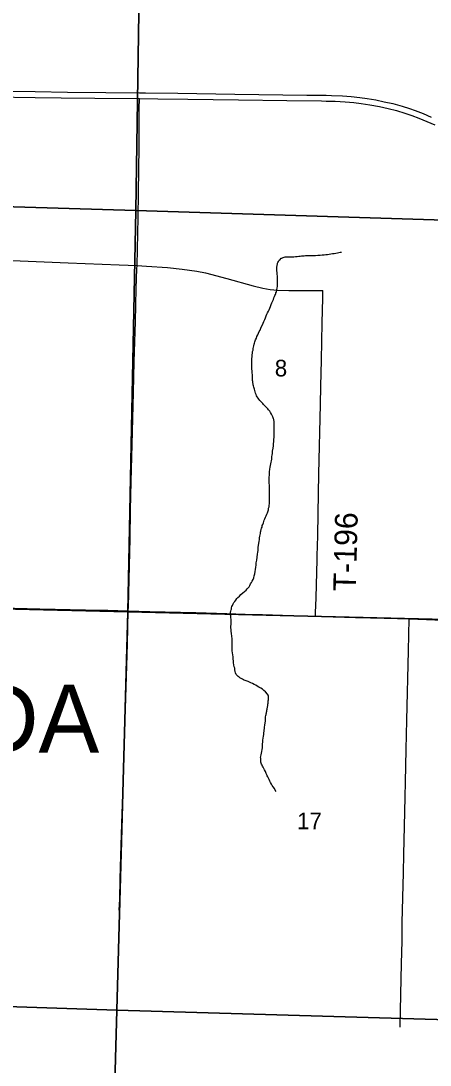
# Model space of a CAD drawing. Extents: x 1587405 to 1714697, y 1028970 to 1155083.
# Drawn here: x 1687215 to 1692632, y 1074942 to 1088767 of the extents above; entities that cross this region are included whole.
import ezdxf

# ---------------------------------------------------------------- set-up
doc = ezdxf.new("R2010")
doc.units = 0
for name, color, linetype in [('GM_X_County_Road', 7, 'Continuous'), ('GM_X_Minor_River', 7, 'Continuous'), ('GM_X_Section', 7, 'Continuous'), ('GM_X_Section_Text', 7, 'Continuous'), ('GM_X_State_Route', 7, 'Continuous'), ('GM_X_Township_Road', 7, 'Continuous'), ('GM_X_Township_Road_Text', 7, 'Continuous'), ('GM_X_Township_Text', 7, 'Continuous')]:
    doc.layers.add(name, color=color, linetype=linetype)

msp = doc.modelspace()

# ---------------------------------------------------------------- linework, layer by layer
at = {"layer": 'GM_X_County_Road'}
for points in [[(1688753, 1085526), (1688767, 1086164), (1688772, 1086492), (1688779, 1087099), (1688782, 1087602), (1688784, 1087737)], [(1682671, 1085938), (1682797, 1085937), (1683536, 1085939), (1683962, 1085937), (1684077, 1085929), (1684289, 1085906), (1684402, 1085886), (1684626, 1085835), (1684770, 1085804), (1685062, 1085754), (1685485, 1085699), (1686089, 1085645), (1686368, 1085629), (1686909, 1085604), (1687204, 1085589), (1687843, 1085564), (1688516, 1085535), (1688753, 1085526)], [(1688636, 1080955), (1688638, 1081011), (1688660, 1081913), (1688668, 1082290), (1688676, 1082668), (1688680, 1082830), (1688688, 1083158), (1688705, 1083847), (1688716, 1084257), (1688731, 1084782), (1688743, 1085225), (1688751, 1085483), (1688753, 1085526)], [(1688753, 1085526), (1688876, 1085521), (1689154, 1085501), (1689350, 1085480), (1689545, 1085452), (1689658, 1085429), (1689943, 1085354), (1690291, 1085258), (1690419, 1085228), (1690516, 1085211), (1690614, 1085202), (1690762, 1085198), (1691212, 1085195)], [(1688518, 1076993), (1688523, 1077140), (1688531, 1077403), (1688540, 1077714), (1688556, 1078272), (1688563, 1078518), (1688590, 1079371), (1688611, 1080092), (1688621, 1080371), (1688625, 1080519), (1688636, 1080955)]]:
    msp.add_lwpolyline(points, dxfattribs=at)
at = {"layer": 'GM_X_Minor_River'}
for points in [[(1690282, 1084388), (1690288, 1084408), (1690292, 1084428), (1690294, 1084448), (1690298, 1084466), (1690302, 1084485), (1690308, 1084501), (1690314, 1084519), (1690320, 1084545), (1690332, 1084565), (1690340, 1084589), (1690350, 1084609), (1690360, 1084631), (1690371, 1084653), (1690381, 1084673), (1690393, 1084697), (1690421, 1084763), (1690431, 1084785), (1690443, 1084815), (1690451, 1084837), (1690461, 1084861), (1690471, 1084883), (1690481, 1084903), (1690492, 1084925), (1690502, 1084943), (1690510, 1084965), (1690520, 1084987), (1690530, 1085012), (1690538, 1085034), (1690548, 1085060), (1690558, 1085078), (1690564, 1085098), (1690572, 1085116), (1690578, 1085130), (1690584, 1085144), (1690588, 1085156), (1690592, 1085168), (1690597, 1085180), (1690601, 1085196), (1690605, 1085212), (1690607, 1085230), (1690611, 1085254), (1690611, 1085274), (1690613, 1085298), (1690613, 1085318), (1690613, 1085340), (1690613, 1085362), (1690611, 1085386), (1690609, 1085413), (1690607, 1085437), (1690605, 1085459), (1690605, 1085477), (1690603, 1085497), (1690603, 1085507), (1690607, 1085527), (1690609, 1085537), (1690611, 1085547), (1690613, 1085557), (1690615, 1085567), (1690624, 1085583), (1690636, 1085597), (1690646, 1085609), (1690660, 1085623), (1690670, 1085627), (1690688, 1085635), (1690700, 1085639), (1690714, 1085641), (1690734, 1085643), (1690754, 1085643), (1690776, 1085643), (1690794, 1085643), (1690810, 1085645), (1690826, 1085645), (1690852, 1085647), (1690871, 1085649), (1690893, 1085650), (1690913, 1085652), (1690931, 1085654), (1690947, 1085656), (1690965, 1085658), (1690983, 1085660), (1691007, 1085660), (1691029, 1085660), (1691051, 1085660), (1691079, 1085660), (1691117, 1085662), (1691145, 1085664), (1691178, 1085666), (1691202, 1085670), (1691228, 1085671), (1691252, 1085673), (1691274, 1085675), (1691296, 1085679), (1691318, 1085681), (1691340, 1085685), (1691360, 1085687), (1691386, 1085693), (1691406, 1085695), (1691425, 1085699), (1691441, 1085703), (1691457, 1085705)], [(1690504, 1082371), (1690506, 1082385), (1690506, 1082401), (1690506, 1082417), (1690508, 1082435), (1690506, 1082453), (1690506, 1082471), (1690506, 1082489), (1690506, 1082509), (1690504, 1082542), (1690504, 1082568), (1690504, 1082592), (1690504, 1082620), (1690502, 1082648), (1690502, 1082678), (1690502, 1082704), (1690505, 1082776), (1690505, 1082798), (1690509, 1082832), (1690515, 1082858), (1690519, 1082881), (1690523, 1082903), (1690529, 1082923), (1690533, 1082943), (1690535, 1082963), (1690537, 1082981), (1690539, 1083001), (1690543, 1083019), (1690545, 1083041), (1690547, 1083069), (1690554, 1083111), (1690558, 1083141), (1690560, 1083169), (1690564, 1083197), (1690564, 1083226), (1690566, 1083256), (1690566, 1083284), (1690566, 1083316), (1690566, 1083342), (1690566, 1083366), (1690566, 1083382), (1690566, 1083400), (1690568, 1083416), (1690568, 1083434), (1690568, 1083452), (1690566, 1083466), (1690564, 1083478), (1690562, 1083488), (1690558, 1083500), (1690554, 1083511), (1690550, 1083525), (1690542, 1083543), (1690532, 1083559), (1690519, 1083583), (1690509, 1083601), (1690495, 1083617), (1690482, 1083631), (1690468, 1083647), (1690454, 1083661), (1690440, 1083675), (1690428, 1083690), (1690416, 1083702), (1690404, 1083714), (1690392, 1083726), (1690380, 1083742), (1690366, 1083758), (1690334, 1083804), (1690328, 1083822), (1690322, 1083840), (1690316, 1083856), (1690310, 1083872), (1690307, 1083889), (1690303, 1083903), (1690297, 1083919), (1690293, 1083935), (1690291, 1083947), (1690289, 1083961), (1690287, 1083971), (1690285, 1083983), (1690285, 1083993), (1690283, 1084005), (1690283, 1084017), (1690283, 1084029), (1690281, 1084043), (1690281, 1084057), (1690279, 1084073), (1690279, 1084085), (1690277, 1084101), (1690275, 1084119), (1690275, 1084135), (1690273, 1084154), (1690271, 1084172), (1690271, 1084192), (1690271, 1084214), (1690271, 1084238), (1690273, 1084264), (1690273, 1084292), (1690275, 1084322), (1690277, 1084344), (1690280, 1084366), (1690282, 1084388)], [(1690057, 1080135), (1690053, 1080153), (1690049, 1080177), (1690045, 1080195), (1690039, 1080217), (1690035, 1080241), (1690031, 1080266), (1690029, 1080292), (1690027, 1080320), (1690023, 1080348), (1690019, 1080374), (1690015, 1080400), (1690013, 1080428), (1690012, 1080472), (1690012, 1080508), (1690010, 1080547), (1690010, 1080585), (1690006, 1080623), (1690002, 1080657), (1689998, 1080687), (1689996, 1080753), (1689998, 1080775), (1689998, 1080795), (1689998, 1080823), (1689998, 1080844), (1689996, 1080862), (1689996, 1080878), (1689994, 1080890), (1689992, 1080902), (1689990, 1080914), (1689991, 1080928), (1689991, 1080942), (1689993, 1080954), (1689999, 1080968), (1690001, 1080980), (1690005, 1080998), (1690009, 1081012), (1690015, 1081028), (1690025, 1081048), (1690035, 1081066), (1690047, 1081082), (1690059, 1081096), (1690075, 1081118), (1690089, 1081132), (1690107, 1081150), (1690128, 1081172), (1690152, 1081194), (1690176, 1081214), (1690196, 1081230), (1690212, 1081248), (1690224, 1081262), (1690236, 1081276), (1690246, 1081292), (1690256, 1081312), (1690268, 1081330), (1690278, 1081350), (1690289, 1081370), (1690297, 1081392), (1690305, 1081418), (1690311, 1081445), (1690317, 1081475), (1690321, 1081505), (1690325, 1081535), (1690329, 1081563), (1690331, 1081591), (1690337, 1081625), (1690348, 1081707), (1690350, 1081733), (1690354, 1081757), (1690356, 1081775), (1690358, 1081798), (1690362, 1081822), (1690364, 1081850), (1690368, 1081874), (1690372, 1081902), (1690374, 1081924), (1690378, 1081946), (1690382, 1081964), (1690386, 1081980), (1690388, 1081996), (1690392, 1082012), (1690396, 1082032), (1690401, 1082050), (1690407, 1082066), (1690411, 1082084), (1690417, 1082100), (1690425, 1082122), (1690431, 1082140), (1690437, 1082156), (1690443, 1082174), (1690453, 1082195), (1690461, 1082215), (1690471, 1082235), (1690479, 1082253), (1690485, 1082267), (1690489, 1082279), (1690491, 1082293), (1690495, 1082315), (1690500, 1082335), (1690502, 1082353), (1690504, 1082371)], [(1690595, 1078564), (1690583, 1078582), (1690571, 1078604), (1690555, 1078626), (1690543, 1078643), (1690533, 1078661), (1690521, 1078683), (1690511, 1078703), (1690501, 1078723), (1690493, 1078743), (1690485, 1078759), (1690477, 1078771), (1690469, 1078787), (1690461, 1078803), (1690451, 1078828), (1690439, 1078850), (1690431, 1078868), (1690421, 1078886), (1690413, 1078900), (1690407, 1078914), (1690401, 1078926), (1690397, 1078938), (1690393, 1078952), (1690391, 1078962), (1690391, 1078974), (1690391, 1078988), (1690391, 1079004), (1690389, 1079016), (1690391, 1079030), (1690395, 1079050), (1690400, 1079072), (1690412, 1079141), (1690414, 1079159), (1690414, 1079173), (1690414, 1079195), (1690416, 1079219), (1690420, 1079243), (1690422, 1079269), (1690426, 1079295), (1690430, 1079321), (1690432, 1079343), (1690436, 1079361), (1690436, 1079377), (1690438, 1079397), (1690440, 1079417), (1690443, 1079442), (1690449, 1079472), (1690451, 1079496), (1690451, 1079516), (1690453, 1079536), (1690455, 1079554), (1690459, 1079570), (1690461, 1079584), (1690463, 1079594), (1690465, 1079604), (1690467, 1079614), (1690469, 1079626), (1690471, 1079640), (1690473, 1079654), (1690475, 1079666), (1690479, 1079678), (1690481, 1079690), (1690483, 1079700), (1690485, 1079712), (1690485, 1079722), (1690487, 1079732), (1690487, 1079742), (1690489, 1079752), (1690489, 1079764), (1690491, 1079778), (1690494, 1079788), (1690494, 1079799), (1690494, 1079817), (1690494, 1079827), (1690490, 1079841), (1690478, 1079855), (1690452, 1079883), (1690430, 1079903), (1690412, 1079917), (1690390, 1079933), (1690367, 1079947), (1690345, 1079958), (1690325, 1079970), (1690303, 1079980), (1690279, 1079994), (1690261, 1080004), (1690243, 1080012), (1690225, 1080020), (1690209, 1080026), (1690195, 1080030), (1690183, 1080034), (1690171, 1080040), (1690161, 1080042), (1690147, 1080050), (1690131, 1080061), (1690115, 1080071), (1690103, 1080079), (1690091, 1080087), (1690075, 1080103), (1690067, 1080113), (1690057, 1080135)]]:
    msp.add_lwpolyline(points, dxfattribs=at)
at = {"layer": 'GM_X_Section'}
for points in [[(1682532, 1091680), (1687836, 1091520), (1688816, 1091499), (1688736, 1086256), (1682413, 1086444)], [(1688816, 1091499), (1693172, 1091402), (1693788, 1091391), (1693674, 1086101), (1688736, 1086256)], [(1682413, 1086418), (1682413, 1086444), (1688736, 1086256), (1688630, 1080942), (1682308, 1081094)], [(1688736, 1086256), (1693674, 1086101), (1693579, 1080823), (1688630, 1080942)], [(1682308, 1081094), (1688630, 1080942), (1688484, 1075671), (1682137, 1075883)], [(1688630, 1080942), (1693579, 1080823), (1693475, 1075523), (1688484, 1075671)], [(1682136, 1075811), (1682137, 1075883), (1688484, 1075671), (1688338, 1070385), (1681969, 1070588)], [(1688484, 1075671), (1693475, 1075523), (1693362, 1070235), (1688338, 1070385)]]:
    msp.add_lwpolyline(points, close=True, dxfattribs=at)
at = {"layer": 'GM_X_State_Route'}
for points in [[(1686797, 1087836), (1687404, 1087830), (1687831, 1087825), (1688340, 1087819), (1688785, 1087813), (1688865, 1087812), (1689292, 1087808), (1690046, 1087798), (1690999, 1087784), (1691256, 1087781), (1691326, 1087779), (1691474, 1087774), (1691588, 1087766), (1691702, 1087754), (1691800, 1087740), (1691913, 1087720), (1692025, 1087697), (1692137, 1087671), (1692263, 1087636), (1692357, 1087607), (1692434, 1087580), (1692541, 1087539), (1692647, 1087494)], [(1686848, 1087761), (1687405, 1087753), (1687750, 1087750), (1688193, 1087744), (1688784, 1087737), (1689030, 1087734), (1689424, 1087729), (1690097, 1087721), (1690736, 1087713), (1691196, 1087707), (1691254, 1087705), (1691377, 1087702), (1691508, 1087695), (1691622, 1087686), (1691720, 1087675), (1691834, 1087657), (1691963, 1087633), (1692076, 1087608), (1692187, 1087579), (1692297, 1087546), (1692391, 1087514), (1692483, 1087480), (1692589, 1087436), (1692694, 1087389)]]:
    msp.add_lwpolyline(points, dxfattribs=at)
at = {"layer": 'GM_X_Township_Road'}
for points in [[(1691115, 1080884), (1691116, 1080931), (1691123, 1081128), (1691136, 1081637), (1691136, 1081686), (1691144, 1081948), (1691149, 1082243), (1691159, 1082768), (1691180, 1083686), (1691187, 1083932), (1691195, 1084277), (1691205, 1084769), (1691213, 1085097), (1691212, 1085195)], [(1682301, 1081106), (1682421, 1081101), (1682529, 1081099), (1682776, 1081093), (1683228, 1081082), (1683543, 1081075), (1683743, 1081071), (1683910, 1081067), (1684136, 1081061), (1684344, 1081056), (1684537, 1081052), (1684783, 1081047), (1685333, 1081033), (1685546, 1081028), (1685775, 1081021), (1686460, 1081007), (1687464, 1080983), (1688071, 1080968), (1688366, 1080963), (1688636, 1080955)], [(1688636, 1080955), (1688923, 1080948), (1689530, 1080932), (1689940, 1080921), (1690186, 1080913), (1690415, 1080907), (1690809, 1080893), (1691115, 1080884)], [(1691115, 1080884), (1691202, 1080882), (1691645, 1080870), (1691842, 1080864), (1692202, 1080855), (1692356, 1080849)], [(1692234, 1075446), (1692243, 1075878), (1692252, 1076289), (1692260, 1076584), (1692263, 1076832), (1692280, 1077487), (1692285, 1077735), (1692292, 1078103), (1692302, 1078492), (1692308, 1078687), (1692317, 1079119), (1692324, 1079507), (1692346, 1080427), (1692356, 1080849)], [(1692356, 1080849), (1692809, 1080833), (1693055, 1080825), (1693235, 1080819), (1693825, 1080808), (1694235, 1080799), (1694907, 1080786), (1695432, 1080778), (1695842, 1080769), (1696055, 1080763), (1696123, 1080763)]]:
    msp.add_lwpolyline(points, dxfattribs=at)

# ---------------------------------------------------------------- texts
at = {"layer": 'GM_X_Section_Text'}
for s, p in [('8', (1690576, 1084059)), ('17', (1690871, 1078064))]:
    msp.add_text(s, height=221, rotation=0, dxfattribs=at).set_placement(p)
at = {"layer": 'GM_X_Township_Road_Text'}
msp.add_text('T-196', height=300, rotation=88.5951, dxfattribs=at).set_placement((1691649, 1081210))
at = {"layer": 'GM_X_Township_Text'}
msp.add_text('AMANDA', height=900, rotation=0, dxfattribs=at).set_placement((1683103, 1079080))

doc.saveas('drawing.dxf')
